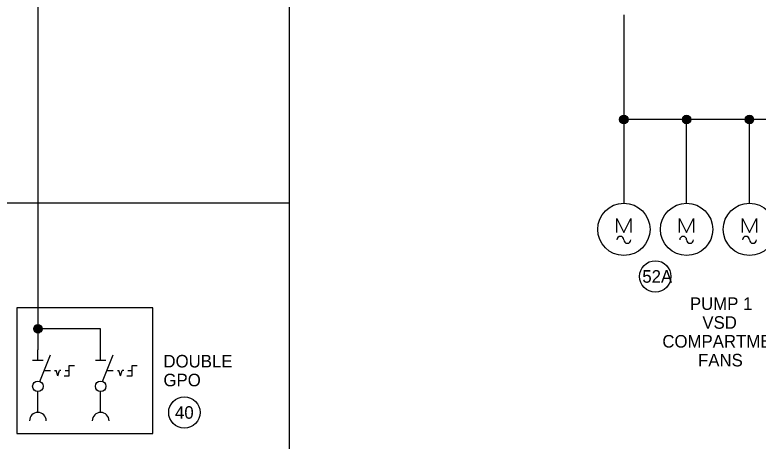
# Model space of a CAD drawing. Extents: x 0 to 841, y 0 to 594.
# Drawn here: x 414.5 to 592.1, y 83.2 to 185 of the extents above; entities that cross this region are included whole.
import ezdxf

# ---------------------------------------------------------------- set-up
doc = ezdxf.new("R2010")
doc.units = 0
doc.layers.add('Level 1', color=7, linetype='Continuous')
doc.layers.add('Level 10', color=7, linetype='Continuous')

msp = doc.modelspace()

# ---------------------------------------------------------------- linework, layer by layer
at = {"layer": 'Level 1'}
for p, q in [((420, 475), (420, 105)), ((480, 420), (480, 57)), ((560, 185), (560, 140)), ((605, 160), (560, 160)), ((575, 140), (575, 160)), ((590, 140), (590, 160)), ((480, 140), (28, 140)), ((435, 110), (420, 110)), ((435, 105), (435, 110)), ((420, 102.5), (420, 105)), ((435, 102.5), (435, 105)), ((420.46, 97.41), (423, 103.75)), ((435.46, 97.41), (438, 103.75)), ((418.75, 102.5), (421.25, 102.5)), ((433.75, 102.5), (436.25, 102.5)), ((420, 90), (420, 95)), ((435, 90), (435, 95))]:
    msp.add_line(p, q, dxfattribs=at)
msp.add_lwpolyline([(415, 85), (447.5, 85), (447.5, 115), (415, 115)], close=True, dxfattribs=at)
for centre, radius in [((567.5, 122.5), 3.75), ((420, 96.25), 1.25), ((435, 96.25), 1.25), ((455, 90), 3.75)]:
    msp.add_circle(centre, radius, dxfattribs=at)
at = {"layer": 'Level 10'}
for p, q in [((559, 160), (560.99, 160)), ((559.05, 160.3), (560.95, 160.3)), ((559.2, 160.6), (560.8, 160.6)), ((559.56, 160.9), (560.44, 160.9)), ((560, 161), (560, 161)), ((574, 160), (575.99, 160)), ((574.05, 160.3), (575.95, 160.3)), ((574.2, 160.6), (575.8, 160.6)), ((574.56, 160.9), (575.44, 160.9)), ((575, 161), (575, 161)), ((589, 160), (590.99, 160)), ((589.05, 160.3), (590.95, 160.3)), ((589.2, 160.6), (590.8, 160.6)), ((589.56, 160.9), (590.44, 160.9)), ((590, 161), (590, 161)), ((559.05, 159.7), (560.95, 159.7)), ((559.2, 159.4), (560.8, 159.4)), ((559.56, 159.1), (560.44, 159.1)), ((574.05, 159.7), (575.95, 159.7)), ((574.2, 159.4), (575.8, 159.4)), ((574.56, 159.1), (575.44, 159.1)), ((589.05, 159.7), (590.95, 159.7)), ((589.2, 159.4), (590.8, 159.4)), ((589.56, 159.1), (590.44, 159.1)), ((558.33, 136.33), (560, 133)), ((558.33, 133), (558.33, 136.33)), ((560, 133), (561.67, 136.33)), ((561.67, 136.33), (561.67, 133)), ((573.33, 136.33), (575, 133)), ((573.33, 133), (573.33, 136.33)), ((575, 133), (576.67, 136.33)), ((576.67, 136.33), (576.67, 133)), ((588.33, 136.33), (590, 133)), ((588.33, 133), (588.33, 136.33)), ((590, 133), (591.67, 136.33)), ((591.67, 136.33), (591.67, 133)), ((419.05, 110.3), (420.95, 110.3)), ((419.2, 110.6), (420.8, 110.6)), ((419.56, 110.9), (420.44, 110.9)), ((420, 111), (420, 111)), ((419, 110), (420.99, 110)), ((419.05, 109.7), (420.95, 109.7)), ((419.2, 109.4), (420.8, 109.4)), ((419.56, 109.1), (420.44, 109.1)), ((427.5, 98.75), (427.5, 101.25)), ((427.5, 101.25), (428.75, 101.25)), ((442.5, 98.75), (442.5, 101.25)), ((442.5, 101.25), (443.75, 101.25)), ((421.5, 100), (423, 100)), ((424, 100), (424.33, 100)), ((424.75, 98.75), (424.33, 100)), ((424.75, 98.75), (425.17, 100)), ((425.5, 100), (425.17, 100)), ((426.5, 100), (427.5, 100)), ((436.5, 100), (438, 100)), ((439, 100), (439.33, 100)), ((439.75, 98.75), (439.33, 100)), ((439.75, 98.75), (440.17, 100)), ((440.5, 100), (440.17, 100)), ((441.5, 100), (442.5, 100)), ((426.25, 98.75), (427.5, 98.75)), ((441.25, 98.75), (442.5, 98.75))]:
    msp.add_line(p, q, dxfattribs=at)
for centre, radius in [((560, 160), 1), ((575, 160), 1), ((590, 160), 1), ((560, 133.75), 6.25), ((575, 133.75), 6.25), ((590, 133.75), 6.25), ((420, 110), 1)]:
    msp.add_circle(centre, radius, dxfattribs=at)
for centre, radius, start, end in [((559.17, 131.25), 0.83, 0, 180), ((574.17, 131.25), 0.83, 0, 180), ((589.17, 131.25), 0.83, 0, 180), ((560.83, 131.25), 0.83, 180, 0), ((575.83, 131.25), 0.83, 180, 0), ((590.83, 131.25), 0.83, 180, 0), ((420, 88), 2, 0, 180), ((435, 88), 2, 0, 180)]:
    msp.add_arc(centre, radius, start, end, dxfattribs=at)

# ---------------------------------------------------------------- texts
at = {"layer": 'Level 1'}
for s, p in [('52A', (564.41, 121)), ('PUMP 1', (575.78, 114.5)), ('VSD', (578.76, 110)), ('COMPARTMENT', (569.2, 105.5)), ('DOUBLE', (450, 100.75)), ('FANS', (577.72, 101)), ('GPO', (450, 96.25)), ('40', (452.76, 88.5))]:
    msp.add_text(s, height=3, dxfattribs=at).set_placement(p)

doc.saveas('drawing.dxf')
